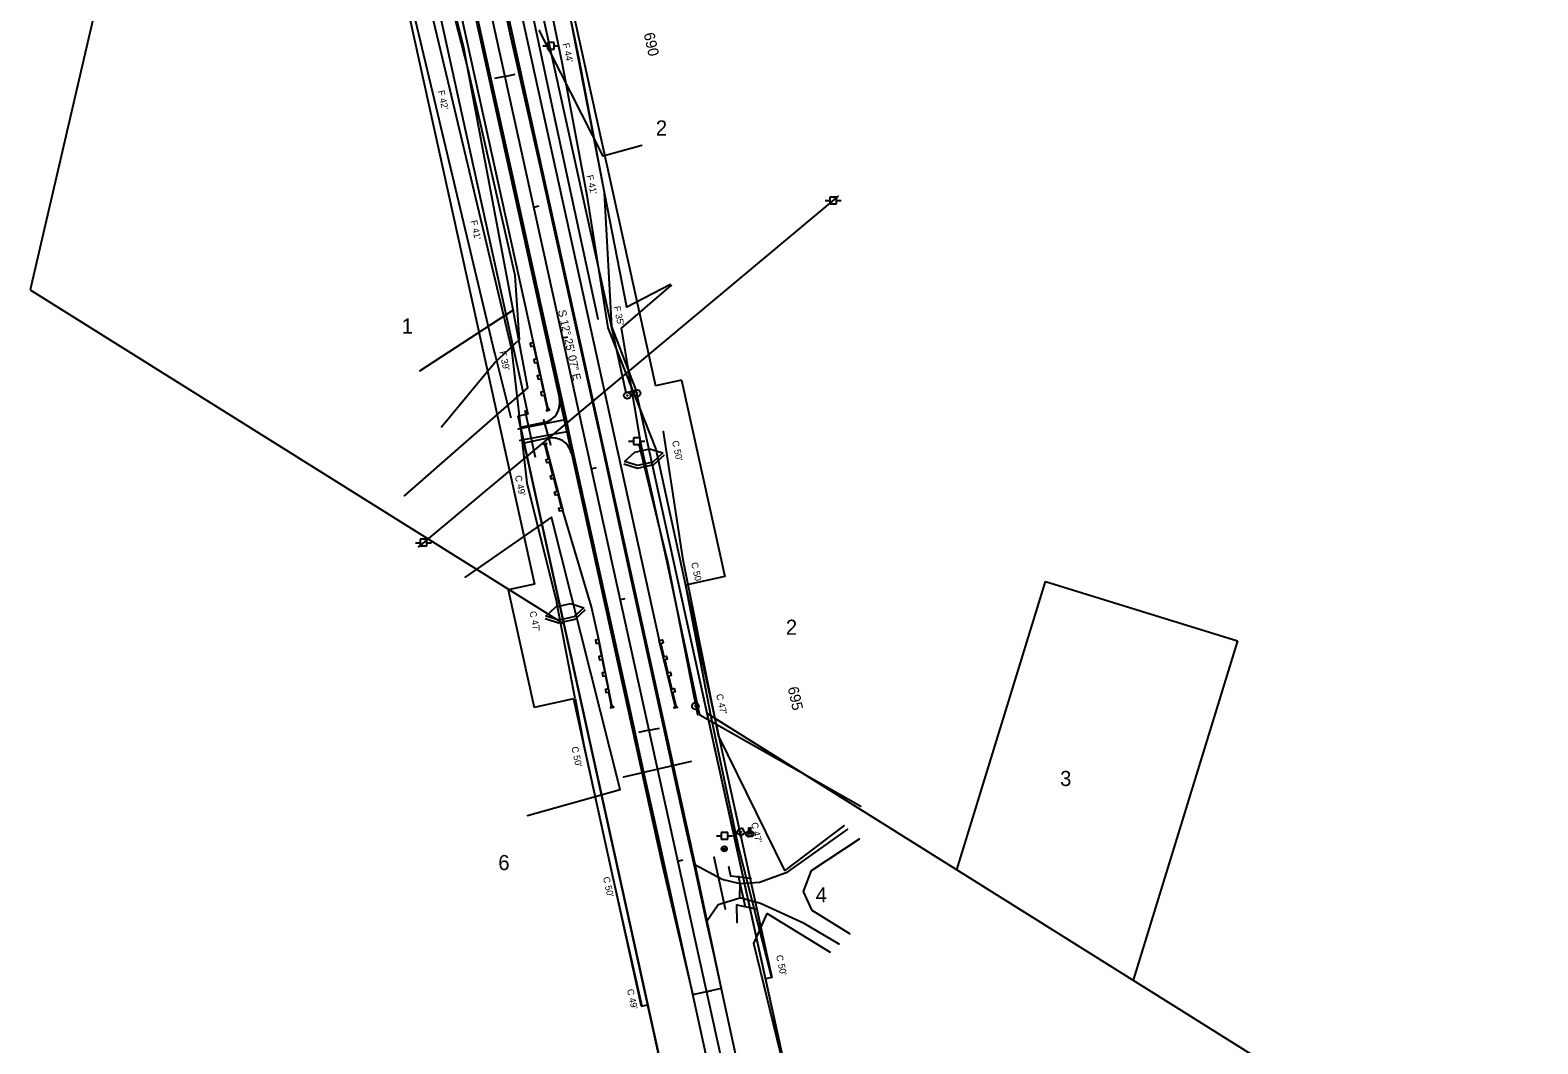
# Model space of a CAD drawing. Extents: x 2519952 to 2531965, y 848341 to 887632.
# Drawn here: x 2521306 to 2522431, y 868173 to 868930 of the extents above; entities that cross this region are included whole.
import ezdxf

# ---------------------------------------------------------------- set-up
doc = ezdxf.new("R2010")
doc.units = 0
for name, color, linetype in [('RD_EV_JW', 7, 'Continuous'), ('RD_EX_DR_Pipe', 7, 'Continuous'), ('RD_EX_Driveway', 7, 'Continuous'), ('RD_EX_DV_Prop', 7, 'Continuous'), ('RD_EX_DV_PropPin', 7, 'Continuous'), ('RD_EX_DV_TX_Prop', 7, 'Continuous'), ('RD_EX_Fence_Other', 7, 'Continuous'), ('RD_EX_H2O', 7, 'Continuous'), ('RD_EX_Road', 7, 'Continuous'), ('RD_EX_RW', 7, 'Continuous'), ('RD_EX_UT', 7, 'Continuous'), ('RD_EX_VEG', 7, 'Continuous'), ('RD_HC_Cl', 7, 'Continuous'), ('RD_HC_Data', 7, 'Continuous'), ('RD_HC_Data_Tic', 7, 'Continuous'), ('RD_HC_TX_Sta50', 7, 'Continuous'), ('RD_PD_CstnLmt', 7, 'Continuous'), ('RD_PD_DR_ErosCtrl', 7, 'Continuous'), ('RD_PD_DR_Pipe', 7, 'Continuous'), ('RD_PD_Driveway', 7, 'Continuous'), ('RD_PD_Final_TrvlWay', 7, 'Continuous'), ('RD_PD_GR', 7, 'Continuous'), ('RD_PD_RW', 7, 'Continuous'), ('RD_PD_TX_CstnLmt', 7, 'Continuous'), ('RD_SMD_Locator', 7, 'Continuous')]:
    doc.layers.add(name, color=color, linetype=linetype)

# ---------------------------------------------------------------- blocks, each defined once
blk = doc.blocks.new('TYPET1')
at = {"layer": 'RD_PD_GR'}
blk.add_lwpolyline([(50, 1), (0, 0), (0, 2.5), (2.4, 2.5), (2.5, 0.5), (12.5, 0.7), (12.4, 2.7), (14.9, 2.8), (15, 0.8), (25, 1), (24.9, 3), (27.4, 3), (27.5, 1), (37.5, 1.2), (37.4, 3.2), (39.9, 3.3), (40, 1.3), (50, 1.5), (51.7, 2.5), (51.7, 0)], close=True, dxfattribs=at)

msp = doc.modelspace()

# ---------------------------------------------------------------- linework, layer by layer
at = {"layer": 'RD_EV_JW'}
for points in [[(2521729.7, 868713.7), (2521695.2, 868873.2), (2521672.8, 868978.7), (2521648.8, 869082), (2521633.3, 869174.5), (2521621.9, 869258.8), (2521602.7, 869268.1)], [(2521612.6, 868633.3), (2521652.3, 868681.3), (2521670.8, 868698.5), (2521667.6, 868746.4), (2521632.6, 868900.1), (2521607.8, 868997.4), (2521589.1, 869078.6), (2521565.7, 869156.4), (2521555.6, 869195.1), (2521545.3, 869232.6)]]:
    msp.add_lwpolyline(points, dxfattribs=at)
at = {"layer": 'RD_EX_DR_Pipe'}
for p, q in [((2521694.2, 868619.9), (2521689.2, 868638.7)), ((2521799.1, 868383.6), (2521748.6, 868371.9)), ((2521824.7, 868273.3), (2521816.2, 868312.1))]:
    msp.add_line(p, q, dxfattribs=at)
at = {"layer": 'RD_EX_Driveway'}
for p, q in [((2521706, 868638.8), (2521669.8, 868631.7)), ((2521707.7, 868630), (2521671.2, 868623.3))]:
    msp.add_line(p, q, dxfattribs=at)
for points in [[(2521915.8, 868333), (2521870.1, 868300.5), (2521850.2, 868293.1), (2521835.6, 868292.1)], [(2521917.6, 868254.8), (2521889.4, 868272.2), (2521883, 868286.5), (2521888.8, 868302), (2521924.8, 868325.7)], [(2521810.4, 868264), (2521819.3, 868276.7), (2521835.3, 868281.6), (2521835.6, 868292.1), (2521822.1, 868295.4), (2521801.2, 868306.5)], [(2521909.6, 868247.1), (2521883.5, 868262.5), (2521850.9, 868277.4), (2521835.3, 868281.6)]]:
    msp.add_lwpolyline(points, dxfattribs=at)
at = {"layer": 'RD_EX_DV_Prop'}
for p, q in [((2521642.9, 869147.3), (2521750.4, 868659)), ((2521569.6, 869131.2), (2521677.2, 868642.9)), ((2521569.6, 869131.2), (2521677.2, 868642.9)), ((2521352.4, 868937.4), (2521305.6, 868735.7)), ((2521305.6, 868735.7), (2521703.9, 868486.4)), ((2521750.4, 868659), (2521757.7, 868660.6)), ((2521757.7, 868660.6), (2521919, 867928.2)), ((2521677.2, 868642.9), (2521669.8, 868641.3)), ((2521831.1, 867908.8), (2521669.8, 868641.3)), ((2521997.4, 868302.7), (2522063.7, 868517.8)), ((2522063.7, 868517.8), (2522207, 868473.7)), ((2522207, 868473.7), (2522129, 868220.3)), ((2521810.8, 868419.5), (2522431.1, 868031.2))]:
    msp.add_line(p, q, dxfattribs=at)
at = {"layer": 'RD_EX_DV_PropPin'}
for centre, radius in [((2521751.4, 868656.8), 2.5), ((2521751.4, 868656.8), 0.25), ((2521758.7, 868658.5), 2.5), ((2521758.7, 868658.5), 0.25), ((2521802.2, 868424.9), 2.5), ((2521802.2, 868424.9), 0.25)]:
    msp.add_circle(centre, radius, dxfattribs=at)
at = {"layer": 'RD_EX_Fence_Other'}
msp.add_lwpolyline([(2521925.8, 868350), (2521805.5, 868418), (2521781.2, 868532.4), (2521761.4, 868621.1), (2521747, 868707), (2521784.2, 868738.8)], dxfattribs=at)
at = {"layer": 'RD_EX_H2O'}
msp.add_line((2521596.6, 868675.1), (2521666.4, 868720.8), dxfattribs=at)
msp.add_lwpolyline([(2521762.3, 868843.4), (2521733.4, 868835.4), (2521685.9, 868929.2)], dxfattribs=at)
at = {"layer": 'RD_EX_Road'}
for p, q in [((2521643.9, 868919.8), (2521622.2, 869017.4)), ((2521664.3, 868925.8), (2521643.4, 869022.4)), ((2521665.7, 868821.4), (2521643.9, 868919.8)), ((2521686.8, 868826), (2521664.3, 868925.8)), ((2521731.7, 868624.5), (2521686.8, 868826)), ((2521686.9, 868724.9), (2521665.7, 868821.4)), ((2521706, 868638.8), (2521686.9, 868724.9)), ((2521707.7, 868630), (2521706, 868638.8)), ((2521710.1, 868619.4), (2521707.7, 868630)), ((2521752.2, 868528.8), (2521731.7, 868624.5)), ((2521730.8, 868524.8), (2521710.1, 868619.4)), ((2521752.5, 868426.9), (2521730.8, 868524.8)), ((2521773.5, 868432.5), (2521752.2, 868528.8)), ((2521785, 868380.2), (2521773.5, 868432.5)), ((2521763.7, 868375.2), (2521752.5, 868426.9)), ((2521794.8, 868335), (2521785, 868380.2)), ((2521774.5, 868327.8), (2521763.7, 868375.2)), ((2521801.2, 868306.5), (2521794.8, 868335)), ((2521795.1, 868233.5), (2521774.5, 868327.8)), ((2521810.4, 868264), (2521801.2, 868306.5)), ((2521815.9, 868239.8), (2521810.4, 868264)), ((2521817.6, 868130.9), (2521795.1, 868233.5)), ((2521838.5, 868136.2), (2521815.9, 868239.8))]:
    msp.add_line(p, q, dxfattribs=at)
at = {"layer": 'RD_EX_RW'}
for p, q in [((2521642.9, 869147.3), (2521750.4, 868659)), ((2521569.6, 869131.2), (2521677.2, 868642.9))]:
    msp.add_line(p, q, dxfattribs=at)
for points in [[(2521750.4, 868659), (2521757.7, 868660.6), (2521919, 867928.2), (2521911.7, 867926.6)], [(2521677.2, 868642.9), (2521669.8, 868641.3), (2521831.1, 867908.8), (2521838.4, 867910.5)]]:
    msp.add_lwpolyline(points, dxfattribs=at)
at = {"layer": 'RD_EX_UT'}
for p, q in [((2521688.3, 868917.8), (2521691.8, 868917.8)), ((2521696.7, 868920.3), (2521691.7, 868920.3)), ((2521691.7, 868920.3), (2521691.7, 868915.3)), ((2521696.7, 868915.3), (2521696.7, 868920.3)), ((2521696.7, 868917.8), (2521700.3, 868917.8)), ((2521691.7, 868915.3), (2521696.7, 868915.3)), ((2521908.8, 868805.7), (2521595.4, 868543.8)), ((2521907.5, 868805), (2521902.5, 868805)), ((2521902.5, 868805), (2521902.5, 868800)), ((2521907.5, 868800), (2521907.5, 868805)), ((2521899, 868802.5), (2521902.5, 868802.5)), ((2521902.5, 868800), (2521907.5, 868800)), ((2521907.4, 868802.5), (2521911, 868802.5)), ((2521760.9, 868625.1), (2521755.9, 868625.1)), ((2521755.9, 868625.1), (2521755.9, 868620.1)), ((2521760.9, 868620.1), (2521760.9, 868625.1)), ((2521752.4, 868622.6), (2521755.9, 868622.6)), ((2521755.9, 868620.1), (2521760.9, 868620.1)), ((2521760.8, 868622.6), (2521764.4, 868622.6)), ((2521593.3, 868546.9), (2521596.7, 868546.9)), ((2521601.7, 868549.5), (2521596.7, 868549.5)), ((2521596.7, 868549.5), (2521596.7, 868544.5)), ((2521596.7, 868544.5), (2521601.7, 868544.5)), ((2521601.6, 868546.9), (2521605.3, 868546.9)), ((2521601.7, 868544.5), (2521601.7, 868549.5)), ((2521826.4, 868330.6), (2521821.4, 868330.6)), ((2521821.4, 868330.6), (2521821.4, 868325.6)), ((2521826.4, 868325.6), (2521826.4, 868330.6)), ((2521842, 868329.3), (2521842, 868334.3)), ((2521843.7, 868329.4), (2521843.7, 868334.4)), ((2521818, 868328), (2521821.4, 868328)), ((2521821.4, 868325.6), (2521826.4, 868325.6)), ((2521822, 868319.1), (2521825.6, 868317.4)), ((2521822.5, 868316.9), (2521825.1, 868319.7)), ((2521826.3, 868328), (2521830, 868328))]:
    msp.add_line(p, q, dxfattribs=at)
for centre in [(2521842, 868329.3), (2521843.7, 868329.4), (2521823.8, 868318.3)]:
    msp.add_circle(centre, 2, dxfattribs=at)
at = {"layer": 'RD_EX_VEG'}
for points in [[(2521585.1, 868581.9), (2521677.1, 868662.6), (2521629.4, 868916.5), (2521556.8, 869210.5), (2521553.9, 869240.3)], [(2521783.6, 868739.6), (2521751, 868722.7), (2521709.8, 868935.1), (2521665.2, 869123.8), (2521647.2, 869234.2)], [(2521913.4, 868335.8), (2521868.9, 868302.2), (2521819.4, 868403), (2521793.1, 868534.1), (2521778.4, 868630)], [(2521804, 868418.4), (2521781.7, 868532.5), (2521760.5, 868619.3)], [(2521676.8, 868343.1), (2521746.1, 868362.7), (2521694.7, 868565.9), (2521630.4, 868521.1)], [(2521843.9, 868296.2), (2521828.7, 868298), (2521827.2, 868304.8)], [(2521833.5, 868263.2), (2521833.2, 868276.6), (2521847.3, 868273.6)], [(2521971.8, 867999.7), (2521917.6, 867944.3), (2521894.9, 868046.4), (2521845.9, 868247.7), (2521855.7, 868269.9), (2521902.8, 868241.2)]]:
    msp.add_lwpolyline(points, dxfattribs=at)
msp.add_circle((2521836.1, 868330.8), 0.25, dxfattribs=at)
for centre, radius, start, end in [((2521834.5, 868330.7), 1.26, 96.4518, 294.734), ((2521835.4, 868332.4), 1.08, 34.9763, 204.756), ((2521837.1, 868332.5), 0.995, 308.7626, 152.0467), ((2521837.9, 868330.6), 1.22, 256.5667, 98.1046), ((2521836.3, 868329.3), 1.32, 166.8827, 5.7589)]:
    msp.add_arc(centre, radius, start, end, dxfattribs=at)
at = {"layer": 'RD_HC_Cl'}
msp.add_line((2521426, 869957.9), (2521982.6, 867430.2), dxfattribs=at)
at = {"layer": 'RD_HC_Data_Tic'}
for p, q in [((2521660, 868895.1), (2521652.2, 868893.4)), ((2521660, 868895.1), (2521667.8, 868896.8)), ((2521681.5, 868797.5), (2521685.4, 868798.3)), ((2521703, 868699.8), (2521706.9, 868700.7)), ((2521724.5, 868602.1), (2521728.4, 868603)), ((2521746, 868504.5), (2521749.9, 868505.3)), ((2521767.5, 868406.8), (2521759.7, 868405.1)), ((2521767.5, 868406.8), (2521775.4, 868408.5)), ((2521789, 868309.2), (2521792.9, 868310)), ((2521810.5, 868211.5), (2521814.5, 868212.4))]:
    msp.add_line(p, q, dxfattribs=at)
at = {"layer": 'RD_PD_CstnLmt'}
for p, q in [((2521682.4, 869002.5), (2521702.7, 868904.5)), ((2521595.5, 868983.3), (2521618.6, 868886)), ((2521702.7, 868904.5), (2521721.3, 868806.2)), ((2521618.6, 868886), (2521641.8, 868788.7)), ((2521721.3, 868806.2), (2521736.9, 868707.3)), ((2521641.8, 868788.7), (2521665, 868691.4)), ((2521736.9, 868707.3), (2521772.6, 868616.8)), ((2521665, 868691.4), (2521676.4, 868591.5)), ((2521772.6, 868616.8), (2521794.9, 868515.2)), ((2521676.4, 868591.5), (2521698.7, 868501.8)), ((2521794.9, 868515.2), (2521813.7, 868417)), ((2521712.5, 868430.5), (2521698.7, 868501.8)), ((2521712.5, 868430.5), (2521718.9, 868395.8)), ((2521813.7, 868417), (2521834.3, 868319.1)), ((2521718.9, 868395.8), (2521740.4, 868298)), ((2521834.3, 868319.1), (2521859.1, 868222.2)), ((2521740.4, 868298), (2521762.2, 868200.9))]:
    msp.add_line(p, q, dxfattribs=at)
at = {"layer": 'RD_PD_DR_ErosCtrl'}
for p, q in [((2521695.2, 869005.1), (2521715.4, 868907.2)), ((2521582.9, 868980.3), (2521606, 868883)), ((2521715.5, 868906.9), (2521734.1, 868808.6)), ((2521606, 868883), (2521629.2, 868785.7)), ((2521734.1, 868808.2), (2521739.7, 868708.3)), ((2521629.2, 868785.7), (2521652.3, 868688.4)), ((2521739.7, 868708.3), (2521757.8, 868660.7)), ((2521652, 868689.9), (2521664.4, 868640.1)), ((2521749.4, 868607.6), (2521756.9, 868614.5)), ((2521756.9, 868614.5), (2521768.2, 868617)), ((2521768.2, 868617), (2521777.9, 868613.9)), ((2521777.9, 868613.9), (2521770.4, 868607.1)), ((2521771.3, 868605.3), (2521779.1, 868612.5)), ((2521748.9, 868605.8), (2521759, 868602.6)), ((2521759.1, 868604.6), (2521749.4, 868607.6)), ((2521759, 868602.6), (2521771.3, 868605.3)), ((2521770.4, 868607.1), (2521759.1, 868604.6)), ((2521698, 868498.9), (2521709.3, 868501.4)), ((2521709.3, 868501.4), (2521719, 868498.3)), ((2521690, 868490.3), (2521700.1, 868487.1)), ((2521690.5, 868492.1), (2521698, 868498.9)), ((2521700.2, 868489), (2521690.5, 868492.1)), ((2521700.1, 868487.1), (2521712.4, 868489.8)), ((2521711.5, 868491.5), (2521700.2, 868489)), ((2521719, 868498.3), (2521711.5, 868491.5)), ((2521712.4, 868489.8), (2521720.2, 868497))]:
    msp.add_line(p, q, dxfattribs=at)
at = {"layer": 'RD_PD_DR_Pipe'}
for p, q in [((2521682.9, 868610.4), (2521675.1, 868645.6)), ((2521839.6, 868274.7), (2521834.4, 868298.2))]:
    msp.add_line(p, q, dxfattribs=at)
at = {"layer": 'RD_PD_Driveway'}
for p, q in [((2521689.3, 868636.7), (2521671.7, 868632.8)), ((2521691.9, 868625), (2521674.3, 868621.1))]:
    msp.add_line(p, q, dxfattribs=at)
for centre, start, end in [((2521686.1, 868651.3), 282.4185, 12.4185), ((2521695.1, 868610.3), 12.4185, 102.4185)]:
    msp.add_arc(centre, 15, start, end, dxfattribs=at)
at = {"layer": 'RD_PD_Final_TrvlWay'}
for p, q in [((2521503.1, 869551.7), (2521777.3, 868306.6)), ((2521526.6, 869556.9), (2521800.8, 868311.7)), ((2521800.8, 868311.7), (2521821.5, 868213.9)), ((2521777.3, 868306.6), (2521800.4, 868209.3)), ((2521821.5, 868213.9), (2521800.4, 868209.3))]:
    msp.add_line(p, q, dxfattribs=at)
at = {"layer": 'RD_PD_GR'}
for p, q in [((2521616.7, 869194.1), (2521775.3, 868473.8)), ((2521681.3, 868696.3), (2521573.7, 869184.6)), ((2521724.7, 868499), (2521703.3, 868570.9)), ((2521730.1, 868474.6), (2521724.7, 868499))]:
    msp.add_line(p, q, dxfattribs=at)
at = {"layer": 'RD_PD_RW'}
for p, q in [((2521664.8, 869152.2), (2521772.4, 868663.9)), ((2521547.7, 869126.4), (2521682.1, 868516)), ((2521791.9, 868668.2), (2521824.2, 868521.7)), ((2521662.5, 868511.7), (2521681.9, 868423.8)), ((2521859.4, 868222.3), (2521854.5, 868221.2)), ((2521761.7, 868200.7), (2521766.6, 868201.8))]:
    msp.add_line(p, q, dxfattribs=at)
for points in [[(2521791.9, 868668.2), (2521772.4, 868663.9)], [(2521824.2, 868521.7), (2521794.9, 868515.2)], [(2521682.1, 868516), (2521662.5, 868511.7)], [(2521794.9, 868515.2), (2521859.4, 868222.3)], [(2521711.2, 868430.2), (2521681.9, 868423.8)], [(2521711.2, 868430.2), (2521761.7, 868200.7)]]:
    msp.add_lwpolyline(points, dxfattribs=at)
at = {"layer": 'RD_SMD_Locator'}
for centre in [(2521685.9, 868929.2), (2521629.4, 868916.5), (2521643.9, 868919.8), (2521664.3, 868925.8), (2521632.6, 868900.1), (2521695.2, 868873.2), (2521762.3, 868843.4), (2521686.8, 868826), (2521733.4, 868835.4), (2521665.7, 868821.4), (2521908.8, 868805.7), (2521667.6, 868746.4), (2521783.6, 868739.6), (2521784.2, 868738.8), (2521686.9, 868724.9), (2521666.4, 868720.8), (2521729.7, 868713.7), (2521751, 868722.7), (2521747, 868707), (2521670.8, 868698.5), (2521652.3, 868681.3), (2521596.6, 868675.1), (2521677.1, 868662.6), (2521689.2, 868638.7), (2521706, 868638.8), (2521706, 868638.8), (2521612.6, 868633.3), (2521669.8, 868631.7), (2521671.2, 868623.3), (2521707.7, 868630), (2521707.7, 868630), (2521731.7, 868624.5), (2521778.4, 868630), (2521694.2, 868619.9), (2521710.1, 868619.4), (2521760.5, 868619.3), (2521761.4, 868621.1), (2521585.1, 868581.9), (2521694.7, 868565.9), (2521595.4, 868543.8), (2521793.1, 868534.1), (2521730.8, 868524.8), (2521752.2, 868528.8), (2521781.2, 868532.4), (2521781.7, 868532.5), (2521630.4, 868521.1), (2521773.5, 868432.5), (2521752.5, 868426.9), (2521804, 868418.4), (2521805.5, 868418), (2521819.4, 868403), (2521785, 868380.2), (2521799.1, 868383.6), (2521748.6, 868371.9), (2521763.7, 868375.2), (2521746.1, 868362.7), (2521676.8, 868343.1), (2521925.8, 868350), (2521794.8, 868335), (2521913.4, 868335.8), (2521915.8, 868333), (2521774.5, 868327.8), (2521924.8, 868325.7), (2521816.2, 868312.1), (2521801.2, 868306.5), (2521801.2, 868306.5), (2521827.2, 868304.8), (2521828.7, 868298), (2521868.9, 868302.2), (2521870.1, 868300.5), (2521888.8, 868302), (2521822.1, 868295.4), (2521835.6, 868292.1), (2521835.6, 868292.1), (2521843.9, 868296.2), (2521850.2, 868293.1), (2521883, 868286.5), (2521819.3, 868276.7), (2521833.2, 868276.6), (2521835.3, 868281.6), (2521835.3, 868281.6), (2521850.9, 868277.4), (2521810.4, 868264), (2521810.4, 868264), (2521824.7, 868273.3), (2521833.5, 868263.2), (2521847.3, 868273.6), (2521855.7, 868269.9), (2521889.4, 868272.2), (2521883.5, 868262.5), (2521917.6, 868254.8), (2521845.9, 868247.7), (2521902.8, 868241.2), (2521909.6, 868247.1), (2521795.1, 868233.5), (2521815.9, 868239.8)]:
    msp.add_circle(centre, 0.001, dxfattribs=at)

# ---------------------------------------------------------------- block references
at = {"layer": 'RD_PD_GR'}
for p, yscale, rotation in [((2521681.3, 868696.3), -1.0000000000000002, -76.4355636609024), ((2521730.1, 868474.6), -1.0000000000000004, -77.58154352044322)]:
    msp.add_blockref('TYPET1', p, dxfattribs=dict(at, yscale=yscale, rotation=rotation))
for p, rotation in [((2521703.3, 868570.9), 103.56313888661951), ((2521775.3, 868473.8), -77.58147915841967)]:
    msp.add_blockref('TYPET1', p, dxfattribs=dict(at, rotation=rotation))

# ---------------------------------------------------------------- texts
at = {"layer": 'RD_EX_DV_TX_Prop'}
for s, p in [('2', (2521772.7, 868850.9)), ('1', (2521583, 868703)), ('2', (2521869.8, 868478.1)), ('3', (2522074.5, 868365.2)), ('6', (2521655.1, 868302.4)), ('4', (2521892, 868278.3))]:
    msp.add_text(s, height=11.3, dxfattribs=at).set_placement(p)
at = {"layer": 'RD_HC_Data'}
msp.add_text('S 12%%d 25\' 07" E', height=6, rotation=282.4185, dxfattribs=at).set_placement((2521699.6, 868720.1))
at = {"layer": 'RD_HC_TX_Sta50'}
for s, p in [('690', (2521763.6, 868926.9)), ('695', (2521871.1, 868438.5))]:
    msp.add_text(s, height=8, rotation=282.4185, dxfattribs=at).set_placement(p)
at = {"layer": 'RD_PD_CstnLmt'}
for s, p in [("F 42'", (2521609.9, 868884.1)), ("F 41'", (2521634.3, 868787.1)), ("F 39'", (2521655.8, 868689.4)), ("C 49'", (2521667.4, 868596.6)), ("C 47'", (2521678.3, 868495.2)), ("C 50'", (2521709.6, 868394.1)), ("C 50'", (2521733.2, 868296.9)), ("C 49'", (2521751.1, 868213.1))]:
    msp.add_text(s, height=5, rotation=282.4185, dxfattribs=at).set_placement(p)
at = {"layer": 'RD_PD_TX_CstnLmt'}
for s, p in [("F 44'", (2521703, 868919.4)), ("F 41'", (2521720.9, 868820.9)), ("F 35'", (2521741.1, 868723)), ("C 50'", (2521784.7, 868622.6)), ("C 50'", (2521799, 868531.7)), ("C 47'", (2521817.7, 868433.4)), ("C 47'", (2521843.8, 868337.5)), ("C 50'", (2521862.4, 868238.5))]:
    msp.add_text(s, height=5, rotation=282.4185, dxfattribs=at).set_placement(p)

doc.saveas('drawing.dxf')
